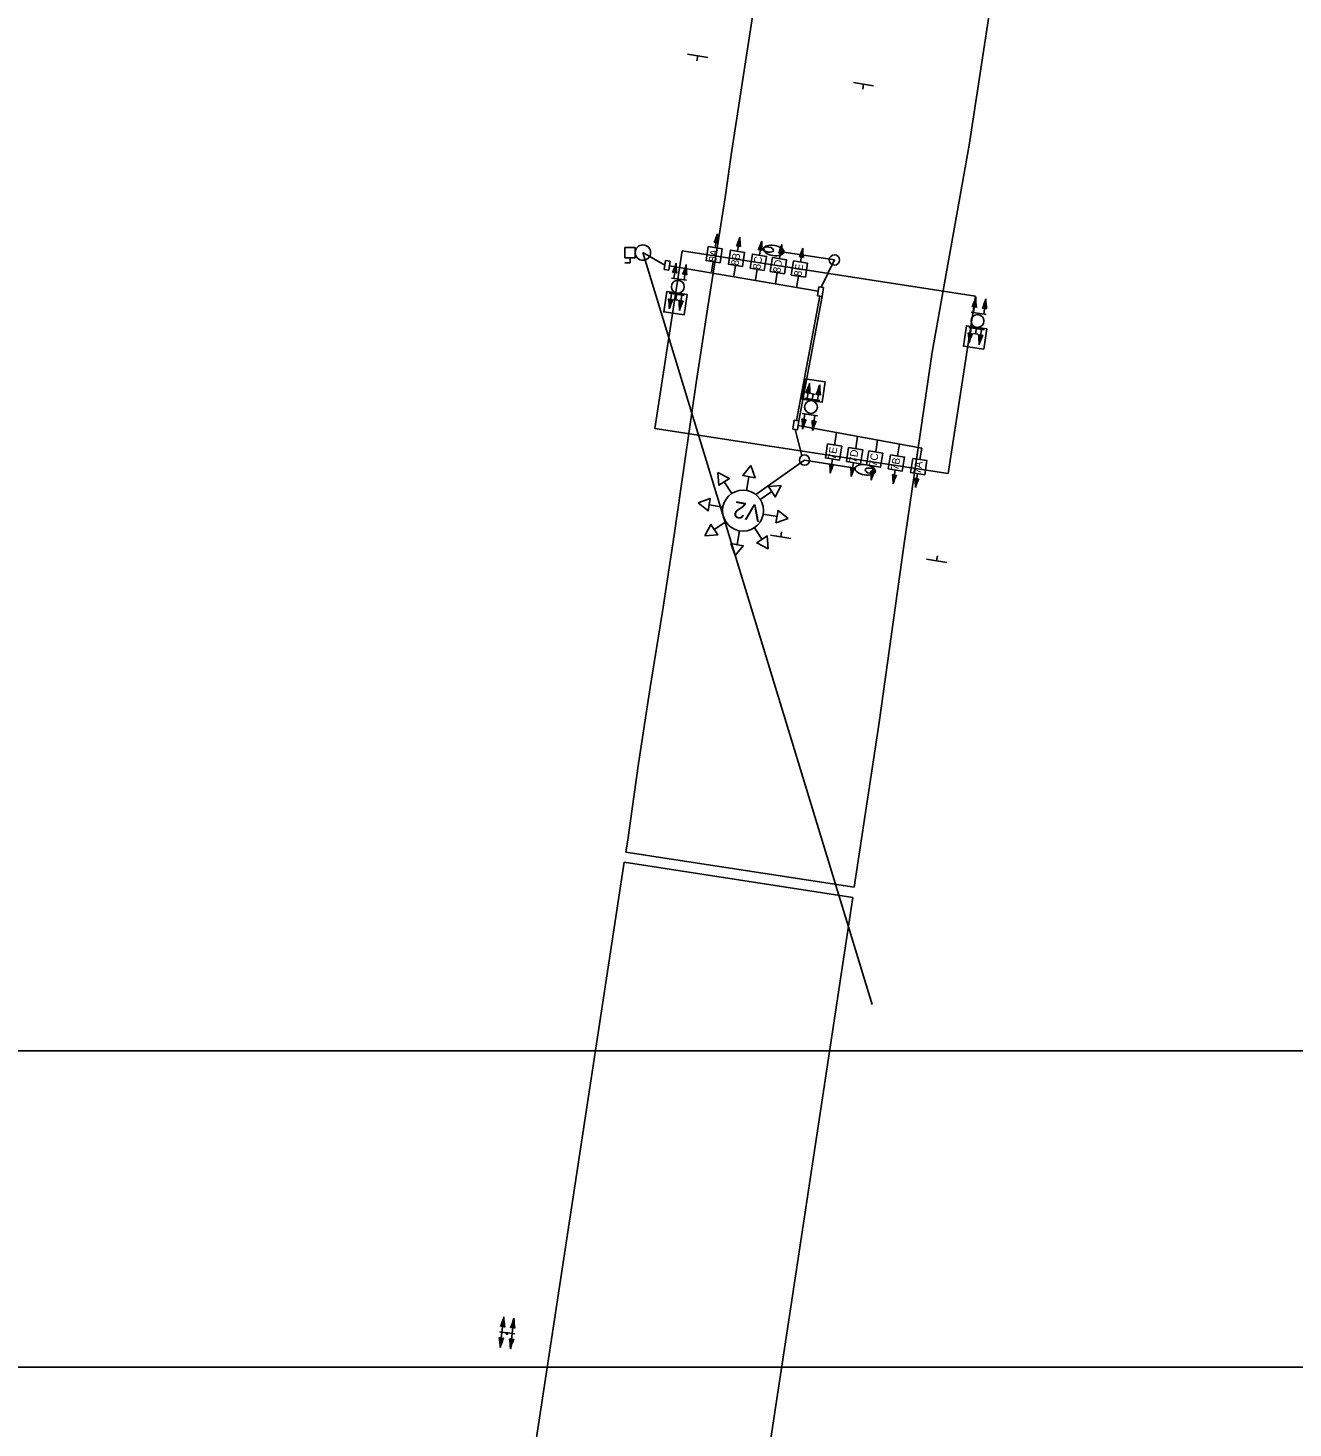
# Model space of a CAD drawing. Extents: x 991933 to 997296, y 1973751 to 1976728.
# Drawn here: x 992879.1 to 993125.8, y 1975371 to 1975643.9 of the extents above; entities that cross this region are included whole.
import ezdxf

# ---------------------------------------------------------------- set-up
doc = ezdxf.new("R2010")
doc.units = 0
for name, color, linetype in [('DSN_DRFT_Common-Annotations', 7, 'Continuous'), ('EX_IRON_PIN', 7, 'Continuous'), ('Level 23', 7, 'Continuous'), ('Level 5', 7, 'Continuous'), ('S_CROSS_DRAIN', 7, 'Continuous'), ('S_CURB', 7, 'Continuous'), ('S_DRIVEWAY', 7, 'Continuous'), ('S_DROP_INLET', 7, 'Continuous'), ('S_PARKING', 7, 'Continuous'), ('S_SIDEWALK', 7, 'Continuous')]:
    doc.layers.add(name, color=color, linetype=linetype)

msp = doc.modelspace()

# ---------------------------------------------------------------- linework, layer by layer
at = {"layer": 'DSN_DRFT_Common-Annotations'}
for p, q in [((993070.74, 1975674.09), (993062.63, 1975621.12)), ((993045.11, 1975508.56), (993040.23, 1975476.44)), ((993040.23, 1975476.44), (992995.69, 1975483.29))]:
    msp.add_line(p, q, dxfattribs=at)
for points in [[(992995.69, 1975483.29), (992995.69, 1975483.29), (992995.69, 1975483.29), (992996.07, 1975485.68), (992998.13, 1975500.54), (993000.43, 1975515.34), (993002.81, 1975530.17), (993005.1, 1975545.07), (993007.26, 1975559.93), (993009.39, 1975574.75), (993011.66, 1975589.56), (993014.03, 1975604.36), (993015.04, 1975610.86), (993016.22, 1975619.18), (993016.22, 1975619.18), (993016.22, 1975619.18), (993016.22, 1975619.18), (993016.22, 1975619.18), (993020.39, 1975646.15), (993020.39, 1975646.15), (993020.39, 1975646.15), (993025.47, 1975681.06)], [(993062.63, 1975621.12), (993055.41, 1975580.76), (993049.93, 1975543.02), (993045.11, 1975508.56)]]:
    msp.add_lwpolyline(points, dxfattribs=at)
at = {"layer": 'EX_IRON_PIN'}
for p, q in [((993001.33, 1975565.89), (993006.66, 1975600.49)), ((993006.66, 1975600.49), (993063.85, 1975591.68)), ((993063.85, 1975591.68), (993058.53, 1975557.09)), ((993058.53, 1975557.09), (993001.33, 1975565.89))]:
    msp.add_line(p, q, dxfattribs=at)
at = {"layer": 'Level 23'}
for points in [[(992705.67, 1975382.9), (993365.67, 1975382.9), (993365.67, 1975802.9), (992705.67, 1975802.9)], [(992469.7, 1974814.53), (993459.71, 1974814.53), (993459.71, 1975444.53), (992469.7, 1975444.53)]]:
    msp.add_lwpolyline(points, close=True, dxfattribs=at)
at = {"layer": 'Level 5'}
for p, q in [((992995.39, 1975481.31), (992950.59, 1975188.29)), ((993039.93, 1975474.46), (992995.39, 1975481.31))]:
    msp.add_line(p, q, dxfattribs=at)
msp.add_lwpolyline([(992997.14, 1975181.55), (993007.15, 1975255.28), (993018.62, 1975333.96), (993027.84, 1975394.67), (993039.93, 1975474.46)], dxfattribs=at)
at = {"layer": 'S_CROSS_DRAIN'}
for p, q in [((993011.69, 1975638.2), (993007.74, 1975638.81)), ((993009.71, 1975638.51), (993009.56, 1975637.52)), ((993011.69, 1975638.2), (993009.71, 1975638.51)), ((993044.01, 1975632.68), (993040.06, 1975633.29)), ((993042.03, 1975632.98), (993041.88, 1975631.99)), ((993044.01, 1975632.68), (993042.03, 1975632.98)), ((993023.92, 1975545.05), (993025.9, 1975544.75)), ((993023.92, 1975545.05), (993027.87, 1975544.44)), ((993025.9, 1975544.75), (993026.05, 1975545.73)), ((993054.31, 1975540.37), (993056.29, 1975540.07)), ((993054.31, 1975540.37), (993058.26, 1975539.76)), ((993056.29, 1975540.07), (993056.44, 1975541.06))]:
    msp.add_line(p, q, dxfattribs=at)
at = {"layer": 'S_CURB'}
for p, q in [((993005.06, 1975595.11), (993005.49, 1975598.1)), ((993007.04, 1975594.83), (993007.47, 1975597.82)), ((993007.53, 1975594.76), (993004.56, 1975595.19)), ((993006.01, 1975594.72), (993006.04, 1975594.97)), ((993004.12, 1975592.22), (993007.08, 1975591.79)), ((993004.61, 1975592.15), (993004.17, 1975589.16)), ((993005.64, 1975592.25), (993005.6, 1975592)), ((993006.58, 1975591.86), (993006.14, 1975588.87)), ((993063.51, 1975588.45), (993063.94, 1975591.44)), ((993065.49, 1975588.16), (993065.92, 1975591.15)), ((993065.98, 1975588.09), (993063.01, 1975588.52)), ((993064.09, 1975585.59), (993064.05, 1975585.34)), ((993064.46, 1975588.06), (993064.49, 1975588.31)), ((993062.57, 1975585.56), (993065.54, 1975585.12)), ((993063.06, 1975585.48), (993062.62, 1975582.5)), ((993065.04, 1975585.19), (993064.6, 1975582.2)), ((993031.06, 1975571.69), (993031.52, 1975574.67)), ((993033.04, 1975571.38), (993033.5, 1975574.37)), ((993033.53, 1975571.31), (993030.56, 1975571.76)), ((993032.01, 1975571.29), (993032.05, 1975571.54)), ((993030.1, 1975568.8), (993033.07, 1975568.35)), ((993030.59, 1975568.72), (993030.14, 1975565.74)), ((993031.62, 1975568.82), (993031.59, 1975568.57)), ((993032.57, 1975568.42), (993032.12, 1975565.44)), ((992971.53, 1975389.68), (992971.88, 1975392.68)), ((992973.52, 1975389.45), (992973.87, 1975392.45)), ((992974.02, 1975389.39), (992971.04, 1975389.74)), ((992971.53, 1975389.68), (992971.19, 1975386.68)), ((992972.37, 1975389.33), (992972.4, 1975389.58)), ((992972.37, 1975389.33), (992972.62, 1975389.3)), ((992972.65, 1975389.55), (992972.4, 1975389.58)), ((992972.65, 1975389.55), (992972.62, 1975389.3)), ((992973.52, 1975389.45), (992973.17, 1975386.45))]:
    msp.add_line(p, q, dxfattribs=at)
for centre, radius in [((993036.36, 1975598.71), 1), ((993005.82, 1975593.49), 1.25), ((993064.27, 1975586.82), 1.25), ((993031.81, 1975570.05), 1.25), ((993030.53, 1975559.71), 1)]:
    msp.add_circle(centre, radius, dxfattribs=at)
for centre, radius, start, end in [((992991.38, 1975602.37), 14.74, 335.4447, 343.1828), ((993020.22, 1975598.21), 14.74, 180.3995, 188.1376), ((992993.36, 1975602.08), 14.74, 335.4447, 343.1828), ((993022.2, 1975597.92), 14.74, 180.3995, 188.1376), ((993005.11, 1975595.5), 0.814, 49.9438, 113.6385), ((993007.09, 1975595.21), 0.814, 49.9438, 113.6385), ((993004.55, 1975591.77), 0.814, 229.7572, 293.4519), ((992989.43, 1975589.11), 14.74, 0.2129, 7.951), ((993049.83, 1975595.7), 14.74, 335.4447, 343.1828), ((993078.67, 1975591.54), 14.74, 180.3995, 188.1376), ((993051.81, 1975595.41), 14.74, 335.4447, 343.1828), ((993080.65, 1975591.25), 14.74, 180.3995, 188.1376), ((993018.26, 1975584.85), 14.74, 155.2581, 162.9962), ((993006.53, 1975591.48), 0.814, 229.7572, 293.4519), ((992991.41, 1975588.82), 14.74, 0.2129, 7.951), ((993020.24, 1975584.56), 14.74, 155.2581, 162.9962), ((993063.56, 1975588.83), 0.814, 49.9438, 113.6385), ((993065.54, 1975588.54), 0.814, 49.9438, 113.6385), ((993063, 1975585.1), 0.814, 229.7572, 293.4519), ((993047.88, 1975582.44), 14.74, 0.2129, 7.951), ((993076.71, 1975578.19), 14.74, 155.2581, 162.9962), ((993064.98, 1975584.81), 0.814, 229.7572, 293.4519), ((993049.86, 1975582.15), 14.74, 0.2129, 7.951), ((993078.69, 1975577.9), 14.74, 155.2581, 162.9962), ((993017.46, 1975579.07), 14.74, 334.9042, 342.6423), ((993046.26, 1975574.64), 14.74, 179.859, 187.5971), ((993031.12, 1975572.07), 0.814, 49.4033, 113.098), ((993019.43, 1975578.77), 14.74, 334.9042, 342.6423), ((993033.1, 1975571.77), 0.814, 49.4033, 113.098), ((993048.24, 1975574.33), 14.74, 179.859, 187.5971), ((993030.54, 1975568.34), 0.814, 229.5899, 293.2846), ((993015.41, 1975565.72), 14.74, 0.0456, 7.7837), ((993044.22, 1975561.38), 14.74, 155.0908, 162.8289), ((993032.51, 1975568.04), 0.814, 229.5899, 293.2846), ((993017.39, 1975565.43), 14.74, 0.0456, 7.7837), ((993046.2, 1975561.09), 14.74, 155.0908, 162.8289), ((992957.66, 1975396.54), 14.74, 337.0766, 344.8147), ((992986.61, 1975393.2), 14.74, 182.0313, 189.7695), ((992959.64, 1975396.31), 14.74, 337.0766, 344.8147), ((992988.59, 1975392.97), 14.74, 182.0313, 189.7695), ((992971.58, 1975390.07), 0.814, 51.5757, 115.2703), ((992973.56, 1975389.84), 0.814, 51.5757, 115.2703), ((992971.49, 1975389.3), 0.814, 231.5757, 295.2703), ((992956.46, 1975386.16), 14.74, 2.0313, 9.7695), ((992985.41, 1975382.82), 14.74, 157.0766, 164.8147), ((992973.48, 1975389.07), 0.814, 231.5757, 295.2703), ((992958.45, 1975385.93), 14.74, 2.0313, 9.7695), ((992987.39, 1975382.59), 14.74, 157.0766, 164.8147)]:
    msp.add_arc(centre, radius, start, end, dxfattribs=at)
at = {"layer": 'S_DRIVEWAY'}
for p, q in [((993003.41, 1975598.59), (993003.18, 1975596.86)), ((993003.18, 1975596.86), (993004.09, 1975596.73)), ((993004.32, 1975598.47), (993003.41, 1975598.59)), ((993004.09, 1975596.73), (993004.32, 1975598.47)), ((993005.64, 1975592.25), (993005.44, 1975590.95)), ((993033.33, 1975593.47), (993033.08, 1975591.73)), ((993033.08, 1975591.73), (993033.99, 1975591.6)), ((993034.24, 1975593.34), (993033.33, 1975593.47)), ((993033.99, 1975591.6), (993034.24, 1975593.34)), ((993005.01, 1975591.01), (993005.88, 1975590.88)), ((993064.09, 1975585.59), (993063.9, 1975584.28)), ((993063.46, 1975584.35), (993064.33, 1975584.22)), ((993032.64, 1975572.52), (993031.78, 1975572.66)), ((993032.01, 1975571.29), (993032.21, 1975572.59)), ((993028.51, 1975567.48), (993028.24, 1975565.75)), ((993029.42, 1975567.34), (993028.51, 1975567.48)), ((993029.14, 1975565.61), (993029.42, 1975567.34)), ((993028.24, 1975565.75), (993029.14, 1975565.61))]:
    msp.add_line(p, q, dxfattribs=at)
at = {"layer": 'S_DROP_INLET'}
msp.add_line((993043.72, 1975453.56), (992999.02, 1975600.15), dxfattribs=at)
for points in [[(993007.62, 1975591.96), (993007.03, 1975588), (993003.07, 1975588.59), (993003.66, 1975592.54)], [(993066.07, 1975585.29), (993065.48, 1975581.34), (993061.53, 1975581.92), (993062.11, 1975585.88)], [(993030.03, 1975571.59), (993030.64, 1975575.55), (993034.59, 1975574.94), (993033.99, 1975570.99)]]:
    msp.add_lwpolyline(points, close=True, dxfattribs=at)
at = {"layer": 'S_PARKING'}
for p, q in [((992995.52, 1975601.15), (992995.52, 1975599.15)), ((992995.52, 1975601.15), (992997.52, 1975601.15)), ((992997.52, 1975601.15), (992997.52, 1975599.15)), ((992999.02, 1975600.15), (993003.29, 1975597.72)), ((992995.52, 1975599.15), (992997.52, 1975599.15)), ((992995.52, 1975598.15), (992996.52, 1975598.15)), ((992996.52, 1975599.15), (992996.52, 1975598.15)), ((993004.21, 1975597.6), (993033.21, 1975592.6)), ((993036.37, 1975598.77), (993033.79, 1975593.4)), ((993033.54, 1975591.67), (993028.96, 1975567.41)), ((993033.99, 1975591.6), (993029.42, 1975567.34)), ((993028.69, 1975565.68), (993030.03, 1975560.58)), ((993029.28, 1975566.47), (993053.4, 1975562.05))]:
    msp.add_line(p, q, dxfattribs=at)
msp.add_circle((992999.02, 1975600.15), 1.5, dxfattribs=at)
at = {"layer": 'S_SIDEWALK'}
for p, q in [((993013.13, 1975601.1), (993013.57, 1975603.83)), ((993017.49, 1975600.41), (993017.93, 1975603.14)), ((993021.74, 1975599.64), (993022.18, 1975602.37)), ((993025.66, 1975598.99), (993026.1, 1975601.72)), ((993036.36, 1975598.71), (993026.48, 1975600.26)), ((993029.76, 1975598.3), (993030.2, 1975601.03)), ((993012.38, 1975596.39), (993012.7, 1975598.35)), ((993016.73, 1975595.6), (993017.06, 1975597.66)), ((993020.98, 1975594.82), (993021.31, 1975596.89)), ((993024.89, 1975594.11), (993025.23, 1975596.24)), ((993028.98, 1975593.37), (993029.33, 1975595.56)), ((993036.8, 1975565.09), (993036.41, 1975562.64)), ((993040.89, 1975564.34), (993040.51, 1975561.95)), ((993044.8, 1975563.63), (993044.43, 1975561.3)), ((993049.05, 1975562.85), (993048.68, 1975560.52)), ((993053.4, 1975562.05), (993053.04, 1975559.82)), ((993030.52, 1975559.66), (993021.05, 1975552.97)), ((993030.52, 1975559.66), (993040.4, 1975558.11)), ((993035.97, 1975559.9), (993035.53, 1975557.17)), ((993040.07, 1975559.21), (993039.63, 1975556.48)), ((993043.99, 1975558.55), (993043.55, 1975555.82)), ((993019.24, 1975553.79), (993019.7, 1975556.47)), ((993048.24, 1975557.78), (993047.8, 1975555.05)), ((993052.6, 1975557.08), (993052.16, 1975554.35)), ((993016.35, 1975553.19), (993014.85, 1975555.46)), ((993021.89, 1975552.05), (993024.16, 1975553.55)), ((993014.61, 1975550.54), (993011.93, 1975551)), ((993015.21, 1975547.65), (993012.94, 1975546.15)), ((993022.49, 1975549.16), (993025.17, 1975548.69)), ((993017.86, 1975545.91), (993017.39, 1975543.23)), ((993020.75, 1975546.51), (993022.25, 1975544.24))]:
    msp.add_line(p, q, dxfattribs=at)
for points in [[(993014.06, 1975598.14), (993011.32, 1975598.58), (993011.76, 1975601.32), (993014.5, 1975600.88)], [(993018.42, 1975597.44), (993015.68, 1975597.88), (993016.12, 1975600.63), (993018.86, 1975600.19)], [(993022.68, 1975596.68), (993019.93, 1975597.12), (993020.38, 1975599.86), (993023.12, 1975599.42)], [(993026.6, 1975596.02), (993023.85, 1975596.47), (993024.3, 1975599.21), (993027.04, 1975598.77)], [(993030.7, 1975595.34), (993027.96, 1975595.78), (993028.4, 1975598.52), (993031.14, 1975598.08)], [(993035.04, 1975562.86), (993037.78, 1975562.42), (993037.34, 1975559.68), (993034.6, 1975560.12)], [(993039.14, 1975562.17), (993041.88, 1975561.73), (993041.44, 1975558.99), (993038.7, 1975559.43)], [(993043.06, 1975561.52), (993045.8, 1975561.07), (993045.36, 1975558.33), (993042.62, 1975558.77)], [(993020.08, 1975558.62), (993018.5, 1975556.68), (993020.91, 1975556.26)], [(993047.31, 1975560.74), (993050.06, 1975560.3), (993049.61, 1975557.56), (993046.87, 1975558)], [(993051.67, 1975560.04), (993054.41, 1975559.6), (993053.97, 1975556.86), (993051.23, 1975557.3)], [(993013.65, 1975557.28), (993013.83, 1975554.79), (993015.87, 1975556.13)], [(993025.98, 1975554.75), (993023.49, 1975554.57), (993024.83, 1975552.53)], [(993009.78, 1975551.38), (993011.72, 1975549.8), (993012.14, 1975552.2)], [(993027.32, 1975548.32), (993025.38, 1975549.89), (993024.96, 1975547.49)], [(993011.12, 1975544.95), (993013.61, 1975545.13), (993012.27, 1975547.17)], [(993023.45, 1975542.42), (993023.27, 1975544.91), (993021.23, 1975543.57)], [(993017.02, 1975541.08), (993018.6, 1975543.02), (993016.19, 1975543.44)]]:
    msp.add_lwpolyline(points, close=True, dxfattribs=at)
msp.add_circle((993018.55, 1975549.85), 4, dxfattribs=at)
for centre, radius, start, end in [((993000.71, 1975607.94), 13.5, 334.5209, 342.2591), ((993013.19, 1975601.45), 0.746, 49.0201, 112.7147), ((993027.07, 1975603.71), 13.5, 179.4757, 187.2138), ((993005.07, 1975607.25), 13.5, 334.5209, 342.2591), ((993031.43, 1975603.01), 13.5, 179.4757, 187.2138), ((993009.32, 1975606.48), 13.5, 334.5209, 342.2591), ((993035.68, 1975602.25), 13.5, 179.4757, 187.2138), ((993017.55, 1975600.76), 0.746, 49.0201, 112.7147), ((993021.8, 1975599.99), 0.746, 49.0201, 112.7147), ((993013.25, 1975605.83), 13.5, 334.5209, 342.2591), ((993025.72, 1975599.34), 0.746, 49.0201, 112.7147), ((993039.6, 1975601.6), 13.5, 179.4757, 187.2138), ((993017.35, 1975605.15), 13.5, 334.5209, 342.2591), ((993029.82, 1975598.65), 0.746, 49.0201, 112.7147), ((993043.7, 1975600.91), 13.5, 179.4757, 187.2138), ((993035.91, 1975559.55), 0.746, 228.9434, 292.6381), ((993022.03, 1975557.31), 13.5, 359.3991, 7.1372), ((993048.38, 1975553.04), 13.5, 154.4443, 162.1824), ((993040.01, 1975558.86), 0.746, 228.9434, 292.6381), ((993026.13, 1975556.62), 13.5, 359.3991, 7.1372), ((993052.48, 1975552.35), 13.5, 154.4443, 162.1824), ((993043.93, 1975558.2), 0.746, 228.9434, 292.6381), ((993030.05, 1975555.96), 13.5, 359.3991, 7.1372), ((993056.4, 1975551.69), 13.5, 154.4443, 162.1824), ((993048.19, 1975557.43), 0.746, 228.9434, 292.6381), ((993034.3, 1975555.19), 13.5, 359.3991, 7.1372), ((993060.65, 1975550.92), 13.5, 154.4443, 162.1824), ((993052.55, 1975556.73), 0.746, 228.9434, 292.6381), ((993038.66, 1975554.49), 13.5, 359.3991, 7.1372), ((993065.01, 1975550.22), 13.5, 154.4443, 162.1824)]:
    msp.add_arc(centre, radius, start, end, dxfattribs=at)
for centre, major_axis in [((993024.5, 1975600.57), (-1.98, 0.31)), ((993023.51, 1975600.73), (0.988, -0.155)), ((993042.37, 1975557.8), (1.98, -0.31)), ((993043.36, 1975557.64), (-0.988, 0.155))]:
    msp.add_ellipse(centre, major_axis=major_axis, ratio=0.5, dxfattribs=at)

# ---------------------------------------------------------------- texts
for s, height, rotation, p in [('8A', 1.489, 81.0947, (993013.28, 1975598.24)), ('8B', 1.489, 81.2506, (993017.65, 1975597.54)), ('8C', 1.489, 81.0947, (993021.9, 1975596.77)), ('8D', 1.489, 81.0947, (993025.82, 1975596.13)), ('8E', 1.489, 81.0947, (993029.92, 1975595.43)), ('7E', 1.489, 81.0947, (993036.56, 1975559.75)), ('7D', 1.489, 81.0947, (993040.66, 1975559.11)), ('7C', 1.489, 81.0947, (993044.58, 1975558.41)), ('7B', 1.489, 81.0947, (993048.83, 1975557.65)), ('7A', 1.489, 81.2506, (993053.2, 1975556.93)), ('V2', 3.25, 170.1027, (993022.24, 1975550.82))]:
    msp.add_text(s, height=height, rotation=rotation, dxfattribs=at).set_placement(p)

doc.saveas('drawing.dxf')
